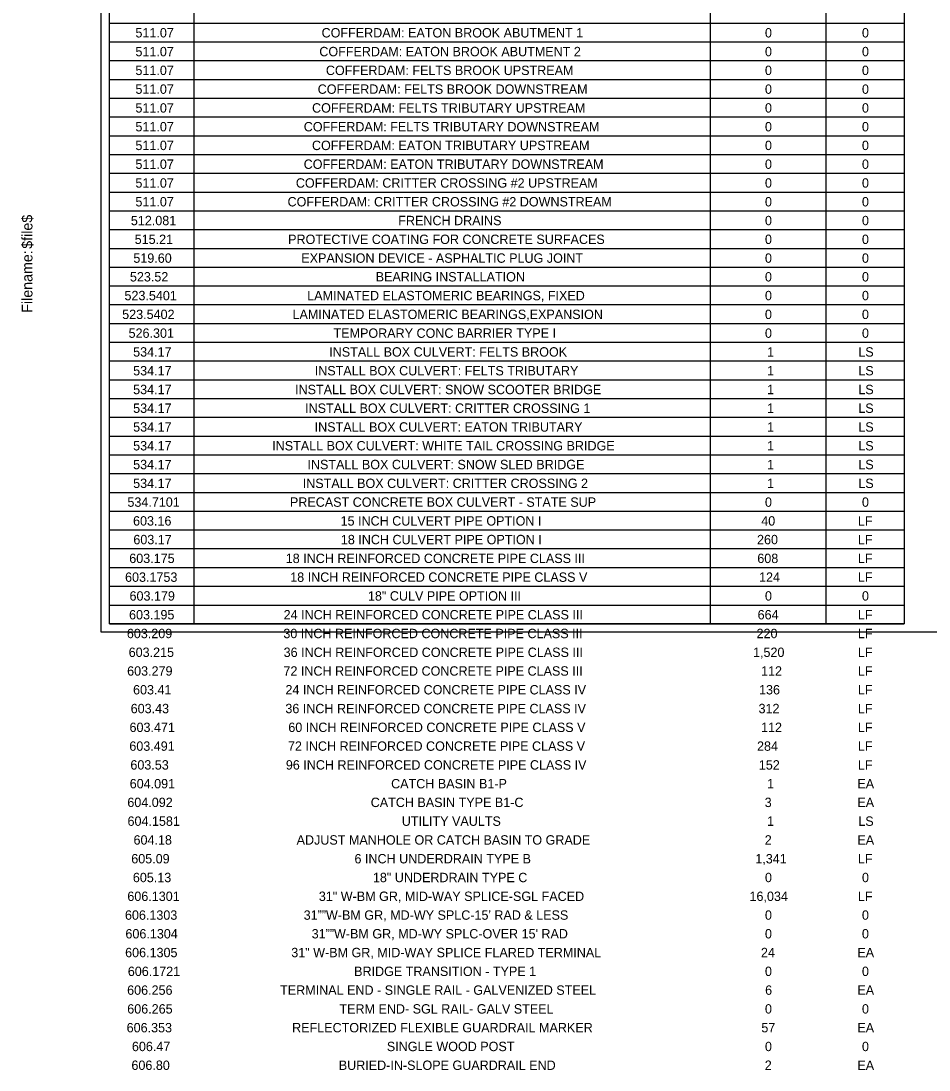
# Model space of a CAD drawing. Extents: x -18.7 to 5.6, y -2.7 to 5.1.
# Drawn here: x -0.084 to 0.868, y -0.459 to 0.641 of the extents above; entities that cross this region are included whole.
import ezdxf

# ---------------------------------------------------------------- set-up
doc = ezdxf.new("R2010")
doc.units = 0
doc.layers.add('ANNOTATION', color=7, linetype='Continuous')
doc.layers.add('BORDER', color=7, linetype='Continuous')

msp = doc.modelspace()

# ---------------------------------------------------------------- linework, layer by layer
at = {"layer": 'BORDER'}
for p, q in [((0.0974, 1.7215), (0.0974, 0.0088)), ((0.6387, 1.7215), (0.6387, 0.0088)), ((0.7601, 1.7215), (0.7601, 0.0088)), ((0.0088, 0.6388), (0.8421, 0.6388)), ((0.0088, 0.6191), (0.8421, 0.6191)), ((0.0088, 0.5994), (0.8421, 0.5994)), ((0.0088, 0.5797), (0.8421, 0.5797)), ((0.0088, 0.56), (0.8421, 0.56)), ((0.0088, 0.5403), (0.8421, 0.5403)), ((0.0088, 0.5207), (0.8421, 0.5207)), ((0.0088, 0.501), (0.8421, 0.501)), ((0.0088, 0.4813), (0.8421, 0.4813)), ((0.0088, 0.4616), (0.8421, 0.4616)), ((0.0088, 0.4419), (0.8421, 0.4419)), ((0.0088, 0.4222), (0.8421, 0.4222)), ((0.0088, 0.4025), (0.8421, 0.4025)), ((0.0088, 0.3829), (0.8421, 0.3829)), ((0.0088, 0.3632), (0.8421, 0.3632)), ((0.0088, 0.3435), (0.8421, 0.3435)), ((0.0088, 0.3238), (0.8421, 0.3238)), ((0.0088, 0.3041), (0.8421, 0.3041)), ((0.0088, 0.2844), (0.8421, 0.2844)), ((0.0088, 0.2647), (0.8421, 0.2647)), ((0.0088, 0.245), (0.8421, 0.245)), ((0.0088, 0.2254), (0.8421, 0.2254)), ((0.0088, 0.2057), (0.8421, 0.2057)), ((0.0088, 0.186), (0.8421, 0.186)), ((0.0088, 0.1663), (0.8421, 0.1663)), ((0.0088, 0.1466), (0.8421, 0.1466)), ((0.0088, 0.1269), (0.8421, 0.1269)), ((0.0088, 0.1072), (0.8421, 0.1072)), ((0.0088, 0.0876), (0.8421, 0.0876)), ((0.0088, 0.0679), (0.8421, 0.0679)), ((0.0088, 0.0482), (0.8421, 0.0482)), ((0.0088, 0.0285), (0.8421, 0.0285)), ((0.0088, 0.0088), (0.8421, 0.0088))]:
    msp.add_line(p, q, dxfattribs=at)
for points in [[(0, 1.75), (2.6667, 1.75), (2.6667, 0), (0, 0)], [(0.0088, 1.7412), (0.8421, 1.7412), (0.8421, 0.0088), (0.0088, 0.0088)]]:
    msp.add_lwpolyline(points, close=True, dxfattribs=at)

# ---------------------------------------------------------------- texts
at = {"layer": 'ANNOTATION'}
for s, height, p in [('511.07', 0.00984, (0.0361, 0.6237)), ('COFFERDAM: EATON BROOK ABUTMENT 1', 0.009843, (0.2313, 0.6237)), ('0', 0.00984, (0.6962, 0.6237)), ('0', 0.00984, (0.7979, 0.6237)), ('511.07', 0.00984, (0.0361, 0.604)), ('COFFERDAM: EATON BROOK ABUTMENT 2', 0.009843, (0.2289, 0.604)), ('0', 0.00984, (0.6962, 0.604)), ('0', 0.00984, (0.7979, 0.604)), ('511.07', 0.00984, (0.0361, 0.5843)), ('COFFERDAM: FELTS BROOK UPSTREAM', 0.009843, (0.2358, 0.5843)), ('0', 0.00984, (0.6962, 0.5843)), ('0', 0.00984, (0.7979, 0.5843)), ('511.07', 0.00984, (0.0361, 0.5646)), ('COFFERDAM: FELTS BROOK DOWNSTREAM', 0.009843, (0.2272, 0.5646)), ('0', 0.00984, (0.6962, 0.5646)), ('0', 0.00984, (0.7979, 0.5646)), ('511.07', 0.00984, (0.0361, 0.5449)), ('COFFERDAM: FELTS TRIBUTARY UPSTREAM', 0.009843, (0.2213, 0.5449)), ('0', 0.00984, (0.6962, 0.5449)), ('0', 0.00984, (0.7979, 0.5449)), ('511.07', 0.00984, (0.0361, 0.5252)), ('COFFERDAM: FELTS TRIBUTARY DOWNSTREAM', 0.009843, (0.2126, 0.5252)), ('0', 0.00984, (0.6962, 0.5252)), ('0', 0.00984, (0.7979, 0.5252)), ('511.07', 0.00984, (0.0361, 0.5056)), ('COFFERDAM: EATON TRIBUTARY UPSTREAM', 0.009843, (0.2212, 0.5056)), ('0', 0.00984, (0.6962, 0.5056)), ('0', 0.00984, (0.7979, 0.5056)), ('511.07', 0.00984, (0.0361, 0.4859)), ('COFFERDAM: EATON TRIBUTARY DOWNSTREAM', 0.009843, (0.2125, 0.4859)), ('0', 0.00984, (0.6962, 0.4859)), ('0', 0.00984, (0.7979, 0.4859)), ('511.07', 0.00984, (0.0361, 0.4662)), ('COFFERDAM: CRITTER CROSSING #2 UPSTREAM', 0.009843, (0.2043, 0.4662)), ('0', 0.00984, (0.6962, 0.4662)), ('0', 0.00984, (0.7979, 0.4662)), ('511.07', 0.00984, (0.0361, 0.4465)), ('COFFERDAM: CRITTER CROSSING #2 DOWNSTREAM', 0.009843, (0.1956, 0.4465)), ('0', 0.00984, (0.6962, 0.4465)), ('0', 0.00984, (0.7979, 0.4465)), ('512.081', 0.00984, (0.0313, 0.4268)), ('FRENCH DRAINS', 0.009843, (0.3117, 0.4268)), ('0', 0.00984, (0.6962, 0.4268)), ('0', 0.00984, (0.7979, 0.4268)), ('515.21', 0.00984, (0.0353, 0.4071)), ('PROTECTIVE COATING FOR CONCRETE SURFACES', 0.009843, (0.1962, 0.4071)), ('0', 0.00984, (0.6962, 0.4071)), ('0', 0.00984, (0.7979, 0.4071)), ('519.60', 0.00984, (0.0339, 0.3874)), ('EXPANSION DEVICE - ASPHALTIC PLUG JOINT', 0.009843, (0.21, 0.3874)), ('0', 0.00984, (0.6962, 0.3874)), ('0', 0.00984, (0.7979, 0.3874)), ('523.52', 0.00984, (0.0303, 0.3678)), ('BEARING INSTALLATION', 0.009843, (0.288, 0.3678)), ('0', 0.00984, (0.6962, 0.3678)), ('0', 0.00984, (0.7979, 0.3678)), ('523.5401', 0.00984, (0.0246, 0.3481)), ('LAMINATED ELASTOMERIC BEARINGS, FIXED', 0.009843, (0.2162, 0.3481)), ('0', 0.00984, (0.6962, 0.3481)), ('0', 0.00984, (0.7979, 0.3481)), ('523.5402', 0.00984, (0.0222, 0.3284)), ('LAMINATED ELASTOMERIC BEARINGS,EXPANSION', 0.009843, (0.2008, 0.3284)), ('0', 0.00984, (0.6962, 0.3284)), ('0', 0.00984, (0.7979, 0.3284)), ('526.301', 0.00984, (0.0289, 0.3087)), ('TEMPORARY CONC BARRIER TYPE I', 0.009843, (0.2438, 0.3087)), ('0', 0.00984, (0.6962, 0.3087)), ('0', 0.00984, (0.7979, 0.3087)), ('534.17', 0.00984, (0.0337, 0.289)), ('INSTALL BOX CULVERT: FELTS BROOK', 0.009843, (0.2393, 0.289)), ('1', 0.00984, (0.6984, 0.289)), ('LS', 0.00984, (0.7941, 0.289)), ('534.17', 0.00984, (0.0337, 0.2693)), ('INSTALL BOX CULVERT: FELTS TRIBUTARY', 0.009843, (0.2241, 0.2693)), ('1', 0.00984, (0.6984, 0.2693)), ('LS', 0.00984, (0.7941, 0.2693)), ('534.17', 0.00984, (0.0337, 0.2496)), ('INSTALL BOX CULVERT: SNOW SCOOTER BRIDGE', 0.009843, (0.2035, 0.2496)), ('1', 0.00984, (0.6984, 0.2496)), ('LS', 0.00984, (0.7941, 0.2496)), ('534.17', 0.00984, (0.0337, 0.23)), ('INSTALL BOX CULVERT: CRITTER CROSSING 1', 0.009843, (0.214, 0.23)), ('1', 0.00984, (0.6984, 0.23)), ('LS', 0.00984, (0.7941, 0.23)), ('534.17', 0.00984, (0.0337, 0.2103)), ('INSTALL BOX CULVERT: EATON TRIBUTARY', 0.009843, (0.224, 0.2103)), ('1', 0.00984, (0.6984, 0.2103)), ('LS', 0.00984, (0.7941, 0.2103)), ('534.17', 0.00984, (0.0337, 0.1906)), ('INSTALL BOX CULVERT: WHITE TAIL CROSSING BRIDGE', 0.009843, (0.1795, 0.1906)), ('1', 0.00984, (0.6984, 0.1906)), ('LS', 0.00984, (0.7941, 0.1906)), ('534.17', 0.00984, (0.0337, 0.1709)), ('INSTALL BOX CULVERT: SNOW SLED BRIDGE', 0.009843, (0.2165, 0.1709)), ('1', 0.00984, (0.6984, 0.1709)), ('LS', 0.00984, (0.7941, 0.1709)), ('534.17', 0.00984, (0.0337, 0.1512)), ('INSTALL BOX CULVERT: CRITTER CROSSING 2', 0.009843, (0.2115, 0.1512)), ('1', 0.00984, (0.6984, 0.1512)), ('LS', 0.00984, (0.7941, 0.1512)), ('534.7101', 0.00984, (0.0277, 0.1315)), ('PRECAST CONCRETE BOX CULVERT - STATE SUP', 0.009843, (0.1981, 0.1315)), ('0', 0.00984, (0.6962, 0.1315)), ('0', 0.00984, (0.7979, 0.1315)), ('603.16', 0.00984, (0.0336, 0.1118)), ('15 INCH CULVERT PIPE OPTION I', 0.009843, (0.2512, 0.1118)), ('40', 0.00984, (0.6923, 0.1118)), ('LF', 0.00984, (0.7937, 0.1118)), ('603.17', 0.00984, (0.0339, 0.0922)), ('18 INCH CULVERT PIPE OPTION I', 0.009843, (0.2515, 0.0922)), ('260', 0.00984, (0.6879, 0.0922)), ('LF', 0.00984, (0.7937, 0.0922)), ('603.175', 0.00984, (0.0296, 0.0725)), ('18 INCH REINFORCED CONCRETE PIPE CLASS III', 0.009843, (0.1937, 0.0725)), ('608', 0.00984, (0.6882, 0.0725)), ('LF', 0.00984, (0.7937, 0.0725)), ('603.1753', 0.00984, (0.0252, 0.0528)), ('18 INCH REINFORCED CONCRETE PIPE CLASS V', 0.009843, (0.1984, 0.0528)), ('124', 0.00984, (0.69, 0.0528)), ('LF', 0.00984, (0.7937, 0.0528)), ('603.179', 0.00984, (0.0299, 0.0331)), ('18" CULV PIPE OPTION III', 0.009843, (0.2799, 0.0331)), ('0', 0.00984, (0.6962, 0.0331)), ('0', 0.00984, (0.7979, 0.0331)), ('603.195', 0.00984, (0.0294, 0.0134)), ('24 INCH REINFORCED CONCRETE PIPE CLASS III', 0.009843, (0.1915, 0.0134)), ('664', 0.00984, (0.6885, 0.0134)), ('LF', 0.00984, (0.7937, 0.0134)), ('603.209', 0.00984, (0.0271, -0.0063)), ('30 INCH REINFORCED CONCRETE PIPE CLASS III', 0.009843, (0.1912, -0.0063)), ('220', 0.00984, (0.6874, -0.0063)), ('LF', 0.00984, (0.7937, -0.0063)), ('603.215', 0.00984, (0.029, -0.026)), ('36 INCH REINFORCED CONCRETE PIPE CLASS III', 0.009843, (0.1915, -0.026)), ('1,520', 0.00984, (0.6837, -0.026)), ('LF', 0.00984, (0.7937, -0.026)), ('603.279', 0.00984, (0.0274, -0.0456)), ('72 INCH REINFORCED CONCRETE PIPE CLASS III', 0.009843, (0.1913, -0.0456)), ('112', 0.00984, (0.6921, -0.0456)), ('LF', 0.00984, (0.7937, -0.0456)), ('603.41', 0.00984, (0.0336, -0.0653)), ('24 INCH REINFORCED CONCRETE PIPE CLASS IV', 0.009843, (0.1934, -0.0653)), ('136', 0.00984, (0.69, -0.0653)), ('LF', 0.00984, (0.7937, -0.0653)), ('603.43', 0.00984, (0.0311, -0.085)), ('36 INCH REINFORCED CONCRETE PIPE CLASS IV', 0.009843, (0.1933, -0.085)), ('312', 0.00984, (0.6895, -0.085)), ('LF', 0.00984, (0.7937, -0.085)), ('603.471', 0.00984, (0.0299, -0.1047)), ('60 INCH REINFORCED CONCRETE PIPE CLASS V', 0.009843, (0.1964, -0.1047)), ('112', 0.00984, (0.6921, -0.1047)), ('LF', 0.00984, (0.7937, -0.1047)), ('603.491', 0.00984, (0.0297, -0.1244)), ('72 INCH REINFORCED CONCRETE PIPE CLASS V', 0.009843, (0.196, -0.1244)), ('284', 0.00984, (0.6879, -0.1244)), ('LF', 0.00984, (0.7937, -0.1244)), ('603.53', 0.00984, (0.0308, -0.1441)), ('96 INCH REINFORCED CONCRETE PIPE CLASS IV', 0.009843, (0.1938, -0.1441)), ('152', 0.00984, (0.6898, -0.1441)), ('LF', 0.00984, (0.7937, -0.1441)), ('604.091', 0.00984, (0.0301, -0.1638)), ('CATCH BASIN B1-P', 0.009843, (0.3042, -0.1638)), ('1', 0.00984, (0.6984, -0.1638)), ('EA', 0.00984, (0.7931, -0.1638)), ('604.092', 0.00984, (0.0276, -0.1834)), ('CATCH BASIN TYPE B1-C', 0.009843, (0.2828, -0.1834)), ('3', 0.00984, (0.6959, -0.1834)), ('EA', 0.00984, (0.7931, -0.1834)), ('604.1581', 0.00984, (0.0278, -0.2031)), ('UTILITY VAULTS', 0.009843, (0.3154, -0.2031)), ('1', 0.00984, (0.6984, -0.2031)), ('LS', 0.00984, (0.7941, -0.2031)), ('604.18', 0.00984, (0.0341, -0.2228)), ('ADJUST MANHOLE OR CATCH BASIN TO GRADE', 0.009843, (0.2051, -0.2228)), ('2', 0.00984, (0.696, -0.2228)), ('EA', 0.00984, (0.7931, -0.2228)), ('605.09', 0.00984, (0.0317, -0.2425)), ('6 INCH UNDERDRAIN TYPE B', 0.009843, (0.2658, -0.2425)), ('1,341', 0.00984, (0.6861, -0.2425)), ('LF', 0.00984, (0.7937, -0.2425)), ('605.13', 0.00984, (0.0334, -0.2622)), ('18" UNDERDRAIN TYPE C', 0.009843, (0.2851, -0.2622)), ('0', 0.00984, (0.6962, -0.2622)), ('0', 0.00984, (0.7979, -0.2622)), ('606.1301', 0.00984, (0.0276, -0.2819)), ('31" W-BM GR, MID-WAY SPLICE-SGL FACED', 0.009843, (0.2284, -0.2819)), ('16,034', 0.00984, (0.68, -0.2819)), ('LF', 0.00984, (0.7937, -0.2819)), ('606.1303', 0.00984, (0.0251, -0.3016)), ("31””W-BM GR, MD-WY SPLC-15' RAD & LESS", 0.009843, (0.2125, -0.3016)), ('0', 0.00984, (0.6962, -0.3016)), ('0', 0.00984, (0.7979, -0.3016)), ('606.1304', 0.00984, (0.0256, -0.3212)), ("31””W-BM GR, MD-WY SPLC-OVER 15' RAD", 0.009843, (0.2209, -0.3212)), ('0', 0.00984, (0.6962, -0.3212)), ('0', 0.00984, (0.7979, -0.3212)), ('606.1305', 0.00984, (0.0253, -0.3409)), ('31" W-BM GR, MID-WAY SPLICE FLARED TERMINAL', 0.009843, (0.1995, -0.3409)), ('24', 0.00984, (0.692, -0.3409)), ('EA', 0.00984, (0.7931, -0.3409)), ('606.1721', 0.00984, (0.0281, -0.3606)), ('BRIDGE TRANSITION - TYPE 1', 0.009843, (0.2654, -0.3606)), ('0', 0.00984, (0.6962, -0.3606)), ('0', 0.00984, (0.7979, -0.3606)), ('606.256', 0.00984, (0.0274, -0.3803)), ('TERMINAL END - SINGLE RAIL - GALVENIZED STEEL', 0.009843, (0.1878, -0.3803)), ('6', 0.00984, (0.6964, -0.3803)), ('EA', 0.00984, (0.7931, -0.3803)), ('606.265', 0.00984, (0.0275, -0.4)), ('TERM END- SGL RAIL- GALV STEEL', 0.009843, (0.25, -0.4)), ('0', 0.00984, (0.6962, -0.4)), ('0', 0.00984, (0.7979, -0.4)), ('606.353', 0.00984, (0.0269, -0.4197)), ('REFLECTORIZED FLEXIBLE GUARDRAIL MARKER', 0.009843, (0.2004, -0.4197)), ('57', 0.00984, (0.6924, -0.4197)), ('EA', 0.00984, (0.7931, -0.4197)), ('606.47', 0.00984, (0.0324, -0.4394)), ('SINGLE WOOD POST', 0.009843, (0.2997, -0.4394)), ('0', 0.00984, (0.6962, -0.4394)), ('0', 0.00984, (0.7979, -0.4394)), ('606.80', 0.00984, (0.0319, -0.4591)), ('BURIED-IN-SLOPE GUARDRAIL END', 0.009843, (0.2493, -0.4591)), ('2', 0.00984, (0.696, -0.4591)), ('EA', 0.00984, (0.7931, -0.4591))]:
    msp.add_text(s, height=height, dxfattribs=at).set_placement(p)
at = {"layer": 'BORDER'}
for s, p in [('$file$', (-0.0719, 0.4021)), ('Filename:', (-0.0719, 0.335))]:
    msp.add_text(s, height=0.01116, rotation=90, dxfattribs=at).set_placement(p)

doc.saveas('drawing.dxf')
